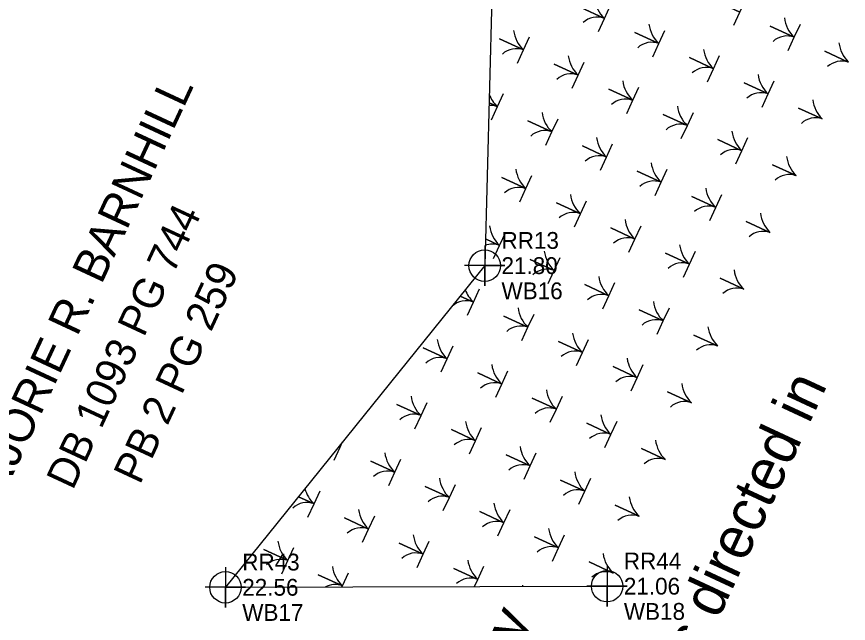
# Model space of a CAD drawing. Extents: x 2532037 to 2533565, y 713396 to 716867.
# Drawn here: x 2532831.4 to 2532955.1, y 715281.6 to 715371.9 of the extents above; entities that cross this region are included whole.
import ezdxf

# ---------------------------------------------------------------- set-up
doc = ezdxf.new("R2010")
doc.units = 0
for name, color, linetype in [('Exist Environmental Wetland Boundary', 7, 'Continuous'), ('Exist Environmental Wetland Boundary Cogo Comment', 7, 'Continuous'), ('Exist Environmental Wetland Boundary Cogo Elevation', 7, 'Continuous'), ('Exist Environmental Wetland Boundary Cogo Number', 7, 'Continuous'), ('Exist Environmental Wetland Boundary Cogo Point CELL', 7, 'Continuous'), ('Exist Property Deed Book Text', 7, 'Continuous'), ('Exist Property Owner Text', 7, 'Continuous'), ('EXIST SURVEY STATEMENT CELL', 7, 'Continuous'), ('Scratch_Level_1', 7, 'Continuous')]:
    doc.layers.add(name, color=color, linetype=linetype)

msp = doc.modelspace()

# ---------------------------------------------------------------- linework, layer by layer
at = {"layer": 'Exist Environmental Wetland Boundary'}
for p, q in [((2532902.53, 715392.38), (2532901.02, 715334.86)), ((2532901.02, 715334.86), (2532862.44, 715286.99)), ((2532862.44, 715286.99), (2532919.23, 715287.15))]:
    msp.add_line(p, q, dxfattribs=at)
at = {"layer": 'Exist Environmental Wetland Boundary Cogo Point CELL'}
for points in [[(2532901.02, 715337.86), (2532901.02, 715331.86), (2532901.02, 715334.86), (2532904.02, 715334.86), (2532898.02, 715334.86)], [(2532862.44, 715289.99), (2532862.44, 715283.99), (2532862.44, 715286.99), (2532865.44, 715286.99), (2532859.44, 715286.99)], [(2532919.23, 715290.15), (2532919.23, 715284.15), (2532919.23, 715287.15), (2532922.23, 715287.15), (2532916.23, 715287.15)]]:
    msp.add_lwpolyline(points, dxfattribs=at)
for centre in [(2532901.02, 715334.86), (2532862.44, 715286.99), (2532919.23, 715287.15)]:
    msp.add_circle(centre, 2.34, dxfattribs=at)
at = {"layer": 'Scratch_Level_1'}
for points in [[(2532938.07, 715370.65), (2532938.97, 715372.6), (2532935.39, 715374.25), (2532938.97, 715372.6), (2532939.87, 715374.55)], [(2532917.93, 715369.7), (2532918.83, 715371.65), (2532915.25, 715373.31), (2532918.83, 715371.65), (2532919.73, 715373.61)], [(2532946.19, 715366.9), (2532947.09, 715368.85), (2532943.51, 715370.5), (2532947.09, 715368.85), (2532948, 715370.8)], [(2532926.05, 715365.95), (2532926.95, 715367.91), (2532923.37, 715369.56), (2532926.95, 715367.91), (2532927.85, 715369.86)], [(2532905.91, 715365.01), (2532906.81, 715366.96), (2532903.23, 715368.61), (2532906.81, 715366.96), (2532907.71, 715368.91)], [(2532955.12, 715365.14), (2532951.63, 715366.76), (2532955.12, 715365.14)], [(2532934.17, 715362.2), (2532935.07, 715364.16), (2532931.49, 715365.81), (2532935.07, 715364.16), (2532935.98, 715366.11)], [(2532914.03, 715361.26), (2532914.93, 715363.21), (2532911.35, 715364.86), (2532914.93, 715363.21), (2532915.83, 715365.16)], [(2532942.29, 715358.45), (2532943.2, 715360.41), (2532939.61, 715362.06), (2532943.2, 715360.41), (2532944.1, 715362.36)], [(2532901.66, 715359.1), (2532902.91, 715358.52), (2532903.81, 715360.47)], [(2532922.15, 715357.51), (2532923.05, 715359.46), (2532919.47, 715361.11), (2532923.05, 715359.46), (2532923.96, 715361.41)], [(2532902.01, 715356.56), (2532902.91, 715358.52), (2532901.66, 715359.1)], [(2532951.24, 715356.69), (2532947.74, 715358.31), (2532951.24, 715356.69)], [(2532910.13, 715352.81), (2532911.03, 715354.77), (2532907.45, 715356.42), (2532911.03, 715354.77), (2532911.94, 715356.72)], [(2532930.27, 715353.76), (2532931.18, 715355.71), (2532927.59, 715357.37), (2532931.18, 715355.71), (2532932.08, 715357.66)], [(2532918.25, 715349.06), (2532919.16, 715351.02), (2532915.57, 715352.67), (2532919.16, 715351.02), (2532920.06, 715352.97)], [(2532938.4, 715350.01), (2532939.3, 715351.96), (2532935.72, 715353.62), (2532939.3, 715351.96), (2532940.2, 715353.91)], [(2532926.38, 715345.31), (2532927.28, 715347.27), (2532923.7, 715348.92), (2532927.28, 715347.27), (2532928.18, 715349.22)], [(2532947.35, 715348.25), (2532943.84, 715349.87), (2532947.35, 715348.25)], [(2532906.23, 715344.37), (2532907.14, 715346.32), (2532903.55, 715347.98), (2532907.14, 715346.32), (2532908.04, 715348.27)], [(2532934.5, 715341.57), (2532935.4, 715343.52), (2532931.82, 715345.17), (2532935.4, 715343.52), (2532936.3, 715345.47)], [(2532914.36, 715340.62), (2532915.26, 715342.57), (2532911.68, 715344.23), (2532915.26, 715342.57), (2532916.16, 715344.52)], [(2532922.48, 715336.87), (2532923.38, 715338.82), (2532919.8, 715340.48), (2532923.38, 715338.82), (2532924.28, 715340.78)], [(2532943.46, 715339.8), (2532939.94, 715341.42), (2532943.46, 715339.8)], [(2532901.12, 715338.85), (2532903.24, 715337.88), (2532904.14, 715339.83)], [(2532902.34, 715335.92), (2532903.24, 715337.88), (2532901.12, 715338.85)], [(2532930.6, 715333.12), (2532931.5, 715335.07), (2532927.92, 715336.73), (2532931.5, 715335.07), (2532932.4, 715337.03)], [(2532910.46, 715332.18), (2532911.36, 715334.13), (2532907.78, 715335.78), (2532911.36, 715334.13), (2532912.26, 715336.08)], [(2532918.58, 715328.43), (2532919.48, 715330.38), (2532915.9, 715332.03), (2532919.48, 715330.38), (2532920.38, 715332.33)], [(2532939.57, 715331.35), (2532936.04, 715332.98), (2532939.57, 715331.35)], [(2532897.38, 715330.34), (2532899.34, 715329.43), (2532900.24, 715331.39)], [(2532898.44, 715327.48), (2532899.34, 715329.43), (2532897.38, 715330.34)], [(2532926.7, 715324.68), (2532927.6, 715326.63), (2532924.02, 715328.28), (2532927.6, 715326.63), (2532928.5, 715328.58)], [(2532906.56, 715323.73), (2532907.46, 715325.68), (2532903.88, 715327.34), (2532907.46, 715325.68), (2532908.36, 715327.64)], [(2532935.68, 715322.9), (2532932.14, 715324.53), (2532935.68, 715322.9)], [(2532914.68, 715319.98), (2532915.58, 715321.93), (2532912, 715323.59), (2532915.58, 715321.93), (2532916.48, 715323.89)], [(2532894.54, 715319.04), (2532895.44, 715320.99), (2532891.86, 715322.64), (2532895.44, 715320.99), (2532896.34, 715322.94)], [(2532922.8, 715316.23), (2532923.7, 715318.18), (2532920.12, 715319.84), (2532923.7, 715318.18), (2532924.6, 715320.14)], [(2532902.66, 715315.29), (2532903.56, 715317.24), (2532899.98, 715318.89), (2532903.56, 715317.24), (2532904.46, 715319.19)], [(2532931.79, 715314.45), (2532928.24, 715316.09), (2532931.79, 715314.45)], [(2532890.64, 715310.59), (2532891.54, 715312.54), (2532887.96, 715314.2), (2532891.54, 715312.54), (2532892.44, 715314.5)], [(2532910.78, 715311.54), (2532911.68, 715313.49), (2532908.1, 715315.14), (2532911.68, 715313.49), (2532912.58, 715315.44)], [(2532918.9, 715307.79), (2532919.8, 715309.74), (2532916.22, 715311.39), (2532919.8, 715309.74), (2532920.71, 715311.69)], [(2532898.76, 715306.84), (2532899.66, 715308.79), (2532896.08, 715310.45), (2532899.66, 715308.79), (2532900.56, 715310.75)], [(2532879.33, 715307.94), (2532879.52, 715307.85), (2532879.88, 715308.62)], [(2532878.62, 715305.9), (2532879.52, 715307.85), (2532879.33, 715307.94)], [(2532927.9, 715306), (2532924.34, 715307.64), (2532927.9, 715306)], [(2532886.74, 715302.15), (2532887.64, 715304.1), (2532884.06, 715305.75), (2532887.64, 715304.1), (2532888.54, 715306.05)], [(2532906.88, 715303.09), (2532907.78, 715305.05), (2532904.2, 715306.7), (2532907.78, 715305.05), (2532908.69, 715307)], [(2532894.86, 715298.4), (2532895.77, 715300.35), (2532892.18, 715302), (2532895.77, 715300.35), (2532896.67, 715302.3)], [(2532915.01, 715299.34), (2532915.91, 715301.3), (2532912.32, 715302.95), (2532915.91, 715301.3), (2532916.81, 715303.25)], [(2532873.31, 715300.47), (2532875.62, 715299.4), (2532876.53, 715301.36)], [(2532874.72, 715297.45), (2532875.62, 715299.4), (2532873.31, 715300.47)], [(2532902.99, 715294.65), (2532903.89, 715296.6), (2532900.3, 715298.25), (2532903.89, 715296.6), (2532904.79, 715298.55)], [(2532924.02, 715297.55), (2532920.45, 715299.2), (2532924.02, 715297.55)], [(2532882.84, 715293.7), (2532883.75, 715295.66), (2532880.16, 715297.31), (2532883.75, 715295.66), (2532884.65, 715297.61)], [(2532911.11, 715290.9), (2532912.01, 715292.85), (2532908.43, 715294.51), (2532912.01, 715292.85), (2532912.91, 715294.8)], [(2532890.97, 715289.95), (2532891.87, 715291.91), (2532888.28, 715293.56), (2532891.87, 715291.91), (2532892.77, 715293.86)], [(2532870.82, 715289.01), (2532871.73, 715290.96), (2532868.14, 715292.61), (2532871.73, 715290.96), (2532872.63, 715292.91)], [(2532899.5, 715287.09), (2532899.99, 715288.16), (2532896.41, 715289.81), (2532899.99, 715288.16), (2532900.89, 715290.11)], [(2532920.13, 715289.1), (2532916.55, 715290.76), (2532920.13, 715289.1)], [(2532879.77, 715287.04), (2532879.85, 715287.21), (2532876.26, 715288.86), (2532879.85, 715287.21), (2532880.75, 715289.16)]]:
    msp.add_lwpolyline(points, dxfattribs=at)
for centre, radius, start, end in [((2532922.12, 715375.16), 4.81, 187.3464, 226.8412), ((2532917.75, 715368.78), 3.07, 69.3593, 132.7539), ((2532950.38, 715372.36), 4.81, 187.3464, 226.8412), ((2532930.24, 715371.41), 4.81, 187.3464, 226.8412), ((2532910.1, 715370.47), 4.81, 187.3464, 226.8412), ((2532946.01, 715365.97), 3.07, 69.3593, 132.7539), ((2532925.87, 715365.03), 3.07, 69.3593, 132.7539), ((2532958.5, 715368.61), 4.81, 187.3464, 225.5699), ((2532905.73, 715364.08), 3.07, 69.3593, 132.7539), ((2532938.36, 715367.66), 4.81, 187.3464, 226.8412), ((2532918.22, 715366.72), 4.81, 187.3464, 226.8412), ((2532954.13, 715362.22), 3.07, 71.2444, 132.7539), ((2532933.99, 715361.28), 3.07, 69.3593, 132.7539), ((2532913.85, 715360.33), 3.07, 69.3593, 132.7539), ((2532946.48, 715363.91), 4.81, 187.3464, 226.8412), ((2532926.34, 715362.97), 4.81, 187.3464, 226.8412), ((2532906.2, 715362.02), 4.81, 200.1826, 226.8412), ((2532942.11, 715357.53), 3.07, 69.3593, 132.7539), ((2532921.97, 715356.58), 3.07, 69.3593, 132.7539), ((2532954.6, 715360.16), 4.81, 187.3464, 225.7081), ((2532901.83, 715355.64), 3.07, 69.3593, 93.4142), ((2532934.46, 715359.22), 4.81, 187.3464, 226.8412), ((2532914.32, 715358.27), 4.81, 187.3464, 226.8412), ((2532950.23, 715353.78), 3.07, 71.0399, 132.7539), ((2532930.09, 715352.83), 3.07, 69.3593, 132.7539), ((2532909.95, 715351.89), 3.07, 69.3593, 132.7539), ((2532942.58, 715355.47), 4.81, 187.3464, 226.8412), ((2532922.44, 715354.52), 4.81, 187.3464, 226.8412), ((2532938.21, 715349.09), 3.07, 69.3593, 132.7539), ((2532918.07, 715348.14), 3.07, 69.3593, 132.7539), ((2532950.71, 715351.72), 4.81, 187.3464, 225.8462), ((2532910.42, 715349.83), 4.81, 187.3464, 226.8412), ((2532930.56, 715350.77), 4.81, 187.3464, 226.8412), ((2532946.33, 715345.34), 3.07, 70.8355, 132.7539), ((2532926.19, 715344.39), 3.07, 69.3593, 132.7539), ((2532906.05, 715343.44), 3.07, 69.3593, 132.7539), ((2532918.54, 715346.08), 4.81, 187.3464, 226.8412), ((2532938.69, 715347.02), 4.81, 187.3464, 226.8412), ((2532934.31, 715340.64), 3.07, 69.3593, 132.7539), ((2532914.17, 715339.7), 3.07, 69.3593, 132.7539), ((2532926.67, 715342.33), 4.81, 187.3464, 226.8412), ((2532946.81, 715343.27), 4.81, 187.3464, 225.9841), ((2532906.52, 715341.38), 4.81, 187.3464, 226.8412), ((2532942.44, 715336.89), 3.07, 70.6311, 132.7539), ((2532902.15, 715335), 3.07, 69.3593, 110.0667), ((2532922.29, 715335.95), 3.07, 69.3593, 132.7539), ((2532914.65, 715337.63), 4.81, 187.3464, 226.8412), ((2532934.79, 715338.58), 4.81, 187.3464, 226.8412), ((2532910.28, 715331.25), 3.07, 69.3593, 132.7539), ((2532930.42, 715332.2), 3.07, 69.3593, 132.7539), ((2532922.77, 715333.88), 4.81, 187.3464, 226.8412), ((2532942.91, 715334.83), 4.81, 187.3464, 226.122), ((2532902.63, 715332.94), 4.81, 200.3993, 226.8412), ((2532918.4, 715327.5), 3.07, 69.3593, 132.7539), ((2532938.54, 715328.45), 3.07, 70.4269, 132.7539), ((2532898.26, 715326.56), 3.07, 69.3593, 132.7539), ((2532930.89, 715330.13), 4.81, 187.3464, 226.8412), ((2532910.75, 715329.19), 4.81, 187.3464, 226.8412), ((2532906.38, 715322.81), 3.07, 69.3593, 132.7539), ((2532926.52, 715323.75), 3.07, 69.3593, 132.7539), ((2532939.01, 715326.39), 4.81, 187.3464, 226.2597), ((2532918.87, 715325.44), 4.81, 187.3464, 226.8412), ((2532898.73, 715324.49), 4.81, 187.3464, 226.8412), ((2532914.5, 715319.06), 3.07, 69.3593, 132.7539), ((2532934.64, 715320), 3.07, 70.2227, 132.7539), ((2532894.36, 715318.11), 3.07, 69.3593, 132.7539), ((2532926.99, 715321.69), 4.81, 187.3464, 226.8412), ((2532906.85, 715320.74), 4.81, 187.3464, 226.8412), ((2532922.62, 715315.31), 3.07, 69.3593, 132.7539), ((2532902.48, 715314.36), 3.07, 69.3593, 132.7539), ((2532935.11, 715317.94), 4.81, 187.3464, 226.3973), ((2532914.97, 715317), 4.81, 187.3464, 226.8412), ((2532894.83, 715316.05), 4.81, 187.3464, 226.8412), ((2532930.74, 715311.56), 3.07, 70.0185, 132.7539), ((2532910.6, 715310.61), 3.07, 69.3593, 132.7539), ((2532890.46, 715309.67), 3.07, 69.3593, 132.7539), ((2532923.09, 715313.25), 4.81, 187.3464, 226.8412), ((2532902.95, 715312.3), 4.81, 187.3464, 226.8412), ((2532918.72, 715306.86), 3.07, 69.3593, 132.7539), ((2532898.58, 715305.92), 3.07, 69.3593, 132.7539), ((2532931.21, 715309.5), 4.81, 187.3464, 226.5348), ((2532878.44, 715304.97), 3.07, 69.3593, 73.4821), ((2532882.81, 715311.35), 4.81, 224.3557, 226.8412), ((2532911.07, 715308.55), 4.81, 187.3464, 226.8412), ((2532890.93, 715307.61), 4.81, 187.3464, 226.8412), ((2532926.84, 715303.11), 3.07, 69.8145, 132.7539), ((2532906.7, 715302.17), 3.07, 69.3593, 132.7539), ((2532886.56, 715301.22), 3.07, 69.3593, 132.7539), ((2532919.19, 715304.8), 4.81, 187.3464, 226.8412), ((2532899.05, 715303.86), 4.81, 187.3464, 226.8412), ((2532878.91, 715302.91), 4.81, 195.0579, 226.8412), ((2532914.82, 715298.42), 3.07, 69.3593, 132.7539), ((2532894.68, 715297.47), 3.07, 69.3593, 132.7539), ((2532927.31, 715301.05), 4.81, 187.3464, 226.6722), ((2532874.54, 715296.53), 3.07, 69.3593, 132.7539), ((2532887.03, 715299.16), 4.81, 187.3464, 226.8412), ((2532907.17, 715300.11), 4.81, 187.3464, 226.8412), ((2532922.94, 715294.67), 3.07, 69.6104, 132.7539), ((2532902.8, 715293.72), 3.07, 69.3593, 132.7539), ((2532882.66, 715292.78), 3.07, 69.3593, 132.7539), ((2532895.15, 715295.41), 4.81, 187.3464, 226.8412), ((2532915.3, 715296.36), 4.81, 187.3464, 226.8412), ((2532875.01, 715294.47), 4.81, 187.3464, 226.8412), ((2532910.92, 715289.97), 3.07, 69.3593, 132.7539), ((2532870.64, 715288.08), 3.07, 69.3593, 132.7539), ((2532890.78, 715289.03), 3.07, 69.3593, 132.7539), ((2532903.28, 715291.66), 4.81, 187.3464, 226.8412), ((2532923.42, 715292.61), 4.81, 187.3464, 226.8094), ((2532883.13, 715290.72), 4.81, 187.3464, 226.8412), ((2532919.05, 715286.23), 3.07, 69.4065, 132.7539), ((2532878.76, 715284.33), 3.07, 69.3593, 118.7744), ((2532898.9, 715285.28), 3.07, 69.3593, 132.7539), ((2532911.4, 715287.91), 4.81, 187.3464, 189.5735)]:
    msp.add_arc(centre, radius, start, end, dxfattribs=at)

# ---------------------------------------------------------------- texts
at = {"layer": 'Exist Environmental Wetland Boundary Cogo Comment'}
for s, p in [('WB16', (2532903.52, 715329.86)), ('WB17', (2532864.94, 715281.99)), ('WB18', (2532921.73, 715282.15))]:
    msp.add_text(s, height=2.5, dxfattribs=at).set_placement(p)
at = {"layer": 'Exist Environmental Wetland Boundary Cogo Elevation'}
for s, p in [('21.80', (2532903.52, 715333.61)), ('22.56', (2532864.94, 715285.74)), ('21.06', (2532921.73, 715285.9))]:
    msp.add_text(s, height=2.5, dxfattribs=at).set_placement(p)
at = {"layer": 'Exist Environmental Wetland Boundary Cogo Number'}
for s, p in [('RR13', (2532903.52, 715337.36)), ('RR43', (2532864.94, 715289.49)), ('RR44', (2532921.73, 715289.65))]:
    msp.add_text(s, height=2.5, dxfattribs=at).set_placement(p)
at = {"layer": 'Exist Property Deed Book Text'}
for s, p in [('DB 1093 PG 744', (2532839.71, 715301.32)), ('PB 2 PG 259', (2532849.7, 715302.14))]:
    msp.add_text(s, height=4.5, rotation=65.05, dxfattribs=at).set_placement(p)
at = {"layer": 'Exist Property Owner Text'}
msp.add_text('MARJORIE R. BARNHILL', height=5, rotation=65.05, dxfattribs=at).set_placement((2532825.02, 715291.19))
at = {"layer": 'EXIST SURVEY STATEMENT CELL'}
for s, p in [('Compilation) performed under my responsible charge meet NCDOT Survey Standards as directed in', (2532795.49, 714980.57)), ('I, Terry K. Wheeler, a Professional Land Surveyor in the state of North Carolina hereby', (2532772.82, 714991.12))]:
    msp.add_text(s, height=6.25, rotation=65.05, dxfattribs=at).set_placement(p)

doc.saveas('drawing.dxf')
